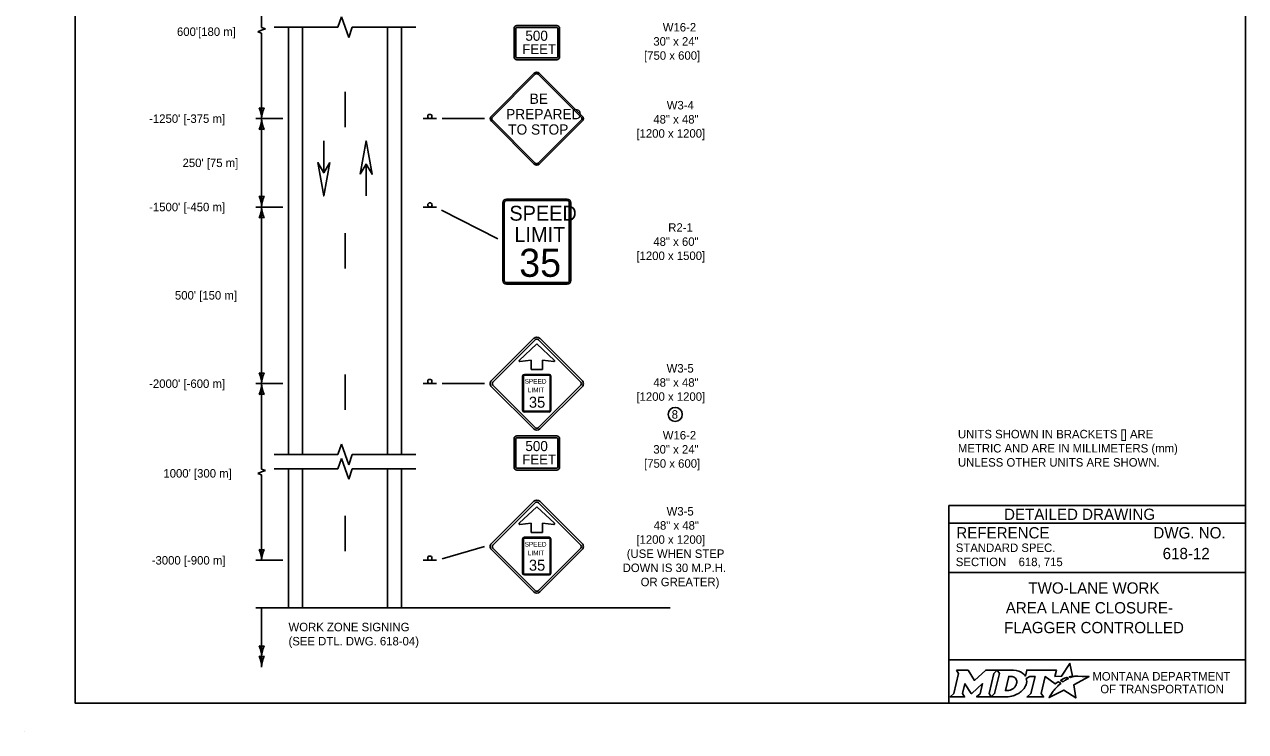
# Model space of a CAD drawing. Extents: x 49991.4 to 50021, y 49987.6 to 50011.4.
# Drawn here: x 49999.98 to 50008.61, y 49999.86 to 50004.87 of the extents above; entities that cross this region are included whole.
import ezdxf

# ---------------------------------------------------------------- set-up
doc = ezdxf.new("R2010")
doc.units = 0
for name, color, linetype in [('Level 1', 7, 'Continuous'), ('Level 2', 7, 'Continuous'), ('Level 3', 7, 'Continuous'), ('Level 6', 7, 'Continuous')]:
    doc.layers.add(name, color=color, linetype=linetype)

msp = doc.modelspace()

# ---------------------------------------------------------------- linework, layer by layer
at = {"layer": 'Level 1'}
for p, q in [((50001.8443, 50001.8221), (50001.8443, 50004.8471)), ((50001.9443, 50004.8119), (50001.9443, 50004.8482)), ((50001.9443, 50001.8221), (50001.9443, 50004.8471)), ((50002.5443, 50001.8221), (50002.5443, 50004.8471)), ((50002.6443, 50001.8221), (50002.6443, 50004.8471)), ((50003.4399, 50004.8376), (50003.4399, 50004.636)), ((50003.4533, 50004.636), (50003.4533, 50004.8376)), ((50003.7423, 50004.8577), (50003.46, 50004.8577)), ((50003.46, 50004.8443), (50003.7423, 50004.8443)), ((50003.749, 50004.8376), (50003.749, 50004.636)), ((50003.7624, 50004.636), (50003.7624, 50004.8376)), ((50003.7423, 50004.6292), (50003.46, 50004.6292)), ((50003.46, 50004.6158), (50003.7423, 50004.6158)), ((50003.5835, 50004.5207), (50003.2794, 50004.2167)), ((50003.9229, 50004.2167), (50003.6188, 50004.5207)), ((50003.5905, 50004.5137), (50003.2865, 50004.2096)), ((50003.9158, 50004.2096), (50003.6118, 50004.5137)), ((50002.2443, 50004.1388), (50002.2443, 50004.3888)), ((50002.8923, 50004.1991), (50002.7963, 50004.1991)), ((50003.2794, 50004.1813), (50003.5835, 50003.8773)), ((50003.2865, 50004.1884), (50003.5905, 50003.8843)), ((50003.6118, 50003.8843), (50003.9158, 50004.1884)), ((50003.6188, 50003.8773), (50003.9229, 50004.1813)), ((50002.094, 50004.0422), (50002.094, 50003.8163)), ((50002.0943, 50004.0422), (50002.0943, 50003.8163)), ((50002.3937, 50003.652), (50002.3937, 50003.8779)), ((50002.394, 50003.652), (50002.394, 50003.8779)), ((50002.8926, 50003.5738), (50002.7966, 50003.5738)), ((50003.361, 50003.6039), (50003.361, 50003.0539)), ((50003.371, 50003.6039), (50003.371, 50003.0539)), ((50003.816, 50003.6289), (50003.386, 50003.6289)), ((50003.816, 50003.6189), (50003.386, 50003.6189)), ((50003.831, 50003.0539), (50003.831, 50003.6039)), ((50003.841, 50003.0539), (50003.841, 50003.6039)), ((50002.2443, 50003.1388), (50002.2443, 50003.3888)), ((50003.386, 50003.0389), (50003.816, 50003.0389)), ((50003.386, 50003.0289), (50003.816, 50003.0289)), ((50003.5796, 50002.6448), (50003.2803, 50002.3455)), ((50003.5897, 50002.6347), (50003.2904, 50002.3354)), ((50003.5796, 50002.6448), (50003.5796, 50002.6448)), ((50003.5897, 50002.6347), (50003.5897, 50002.6347)), ((50003.9116, 50002.3354), (50003.6123, 50002.6347)), ((50003.9217, 50002.3455), (50003.6224, 50002.6448)), ((50003.601, 50002.6063), (50003.4766, 50002.489)), ((50003.7254, 50002.489), (50003.601, 50002.6063)), ((50003.4806, 50002.4804), (50003.5607, 50002.4904)), ((50003.5607, 50002.4904), (50003.5607, 50002.4249)), ((50003.6413, 50002.4249), (50003.6413, 50002.4904)), ((50003.6413, 50002.4904), (50003.7213, 50002.4804)), ((50002.2443, 50002.1388), (50002.2443, 50002.3888)), ((50003.5006, 50002.136), (50003.5006, 50002.3773)), ((50003.5058, 50002.136), (50003.5058, 50002.3773)), ((50003.5131, 50002.3898), (50003.6878, 50002.3898)), ((50003.5131, 50002.3846), (50003.6878, 50002.3846)), ((50003.5607, 50002.4249), (50003.6413, 50002.4249)), ((50003.6005, 50002.3898), (50003.6005, 50002.3898)), ((50003.6951, 50002.3773), (50003.6951, 50002.136)), ((50003.7003, 50002.3773), (50003.7003, 50002.136)), ((50002.8923, 50002.3241), (50002.7963, 50002.3241)), ((50003.2803, 50002.3027), (50003.5796, 50002.0034)), ((50003.2904, 50002.3128), (50003.5897, 50002.0135)), ((50003.6123, 50002.0135), (50003.9116, 50002.3128)), ((50003.6224, 50002.0034), (50003.9217, 50002.3027)), ((50003.6878, 50002.1288), (50003.5131, 50002.1288)), ((50003.6878, 50002.1236), (50003.5131, 50002.1236)), ((50003.4397, 50001.9344), (50003.4397, 50001.7328)), ((50003.4531, 50001.7328), (50003.4531, 50001.9344)), ((50003.7421, 50001.9546), (50003.4599, 50001.9546)), ((50003.4599, 50001.9411), (50003.7421, 50001.9411)), ((50003.7488, 50001.9344), (50003.7488, 50001.7328)), ((50003.7623, 50001.7328), (50003.7623, 50001.9344)), ((50001.8443, 50000.7385), (50001.8443, 50001.7221)), ((50001.9443, 50000.7385), (50001.9443, 50001.7221)), ((50002.5443, 50000.7385), (50002.5443, 50001.7221)), ((50002.6443, 50000.7385), (50002.6443, 50001.7221)), ((50003.7421, 50001.7261), (50003.4599, 50001.7261)), ((50003.4599, 50001.7126), (50003.7421, 50001.7126)), ((50003.5796, 50001.4918), (50003.2803, 50001.1925)), ((50003.5897, 50001.4817), (50003.2904, 50001.1824)), ((50003.601, 50001.4533), (50003.4766, 50001.336)), ((50003.5796, 50001.4918), (50003.5796, 50001.4918)), ((50003.5897, 50001.4817), (50003.5897, 50001.4817)), ((50003.7254, 50001.336), (50003.601, 50001.4533)), ((50003.9116, 50001.1824), (50003.6123, 50001.4817)), ((50003.9217, 50001.1925), (50003.6224, 50001.4918)), ((50002.2443, 50001.1388), (50002.2443, 50001.3888)), ((50003.4806, 50001.3274), (50003.5607, 50001.3374)), ((50003.5607, 50001.3374), (50003.5607, 50001.2719)), ((50003.6413, 50001.2719), (50003.6413, 50001.3374)), ((50003.6413, 50001.3374), (50003.7213, 50001.3274)), ((50003.5131, 50001.2368), (50003.6878, 50001.2368)), ((50003.5607, 50001.2719), (50003.6413, 50001.2719)), ((50003.6005, 50001.2368), (50003.6005, 50001.2368)), ((50003.2803, 50001.1497), (50003.5796, 50000.8504)), ((50003.2904, 50001.1598), (50003.5897, 50000.8605)), ((50003.5006, 50000.983), (50003.5006, 50001.2243)), ((50003.5058, 50000.983), (50003.5058, 50001.2243)), ((50003.5131, 50001.2316), (50003.6878, 50001.2316)), ((50003.6123, 50000.8605), (50003.9116, 50001.1598)), ((50003.6224, 50000.8504), (50003.9217, 50001.1497)), ((50003.6951, 50001.2243), (50003.6951, 50000.983)), ((50003.7003, 50001.2243), (50003.7003, 50000.983)), ((50002.8923, 50001.0741), (50002.7963, 50001.0741)), ((50003.6878, 50000.9758), (50003.5131, 50000.9758)), ((50003.6878, 50000.9706), (50003.5131, 50000.9706)), ((49999.9766, 49999.8624), (49999.9766, 49999.8624))]:
    msp.add_line(p, q, dxfattribs=at)
for points in [[(50008.6146, 50011.2628), (50000.3356, 50011.2628), (50000.3356, 50000.0624), (50008.6146, 50000.0624)], [(50002.352, 50003.8056), (50002.3937, 50004.0421), (50002.4356, 50003.8056), (50002.3937, 50003.8778)], [(50002.136, 50003.8886), (50002.0943, 50003.6521), (50002.0524, 50003.8886), (50002.0943, 50003.8164)]]:
    msp.add_lwpolyline(points, close=True, dxfattribs=at)
for centre in [(50002.8443, 50004.2144), (50002.8446, 50003.5891), (50002.8443, 50002.3394), (50002.8443, 50001.0893)]:
    msp.add_circle(centre, 0.0152, dxfattribs=at)
for centre, radius, start, end in [((50003.46, 50004.8376), 0.0202, 90, 180), ((50003.46, 50004.8376), 0.00672, 90, 180), ((50003.7423, 50004.8376), 0.0202, 0, 90), ((50003.7423, 50004.8376), 0.00672, 0, 90), ((50003.46, 50004.636), 0.0202, 180, 270), ((50003.46, 50004.636), 0.00672, 180, 270), ((50003.7423, 50004.636), 0.00672, 270, 360), ((50003.7423, 50004.636), 0.0202, 270, 360), ((50003.6011, 50004.5031), 0.025, 45, 135), ((50003.6011, 50004.5031), 0.015, 45, 135), ((50003.2971, 50004.1991), 0.025, 135, 225), ((50003.2971, 50004.1991), 0.015, 135, 225), ((50003.9052, 50004.1991), 0.015, 315, 45.00024), ((50003.9052, 50004.1991), 0.025, 315, 45.00024), ((50003.6011, 50003.895), 0.025, 225, 314.99957), ((50003.6011, 50003.895), 0.015, 225, 314.99957), ((50003.386, 50003.6039), 0.025, 90, 180), ((50003.386, 50003.6039), 0.015, 90, 180), ((50003.816, 50003.6039), 0.025, 0, 90), ((50003.816, 50003.6039), 0.015, 0, 90), ((50003.386, 50003.0539), 0.025, 180, 270), ((50003.386, 50003.0539), 0.015, 180, 270), ((50003.816, 50003.0539), 0.025, 270, 0), ((50003.816, 50003.0539), 0.015, 270, 0), ((50003.601, 50002.6234), 0.0302, 45.00007, 134.99993), ((50003.601, 50002.6234), 0.016, 45.00007, 134.99993), ((50003.4801, 50002.4854), 0.00508, 134.62874, 275.82948), ((50003.7218, 50002.4854), 0.00509, 264.38259, 45.16491), ((50003.5131, 50002.3773), 0.0125, 90, 180), ((50003.5131, 50002.3773), 0.00728, 90, 180), ((50003.6878, 50002.3773), 0.0125, 360, 90), ((50003.6878, 50002.3773), 0.00728, 360, 90), ((50003.3017, 50002.3241), 0.0302, 134.99993, 225.00008), ((50003.3017, 50002.3241), 0.016, 134.99993, 225.00008), ((50003.9003, 50002.3241), 0.016, 314.99993, 45.00007), ((50003.9003, 50002.3241), 0.0302, 314.99993, 45.00008), ((50003.5131, 50002.136), 0.0125, 180, 270), ((50003.5131, 50002.136), 0.00728, 180, 270), ((50003.6878, 50002.136), 0.00728, 270, 360), ((50003.6878, 50002.136), 0.0125, 270, 360), ((50003.601, 50002.0248), 0.016, 225.00007, 314.99993), ((50003.4599, 50001.9344), 0.0202, 90, 180), ((50003.4599, 50001.9344), 0.00672, 90, 180), ((50003.601, 50002.0248), 0.0302, 225.00007, 314.99993), ((50003.7421, 50001.9344), 0.0202, 0, 90), ((50003.7421, 50001.9344), 0.00672, 0, 90), ((50003.4599, 50001.7328), 0.0202, 180, 270), ((50003.4599, 50001.7328), 0.00672, 180, 270), ((50003.7421, 50001.7328), 0.00672, 270, 360), ((50003.7421, 50001.7328), 0.0202, 270, 360), ((50003.601, 50001.4704), 0.0302, 45.00007, 134.99993), ((50003.601, 50001.4704), 0.016, 45.00007, 134.99993), ((50003.4801, 50001.3324), 0.00508, 134.62874, 275.82948), ((50003.7218, 50001.3324), 0.00509, 264.38259, 45.16491), ((50003.5131, 50001.2243), 0.0125, 90, 180), ((50003.6878, 50001.2243), 0.0125, 360, 90), ((50003.3017, 50001.1711), 0.0302, 134.99993, 225.00008), ((50003.3017, 50001.1711), 0.016, 134.99993, 225.00008), ((50003.5131, 50001.2243), 0.00728, 90, 180), ((50003.6878, 50001.2243), 0.00728, 360, 90), ((50003.9003, 50001.1711), 0.016, 314.99993, 45.00007), ((50003.9003, 50001.1711), 0.0302, 314.99993, 45.00008), ((50003.5131, 50000.983), 0.0125, 180, 270), ((50003.5131, 50000.983), 0.00728, 180, 270), ((50003.6878, 50000.983), 0.00728, 270, 360), ((50003.6878, 50000.983), 0.0125, 270, 360), ((50003.601, 50000.8718), 0.0302, 225.00007, 314.99993), ((50003.601, 50000.8718), 0.016, 225.00007, 314.99993)]:
    msp.add_arc(centre, radius, start, end, dxfattribs=at)
at = {"layer": 'Level 2'}
for p, q in [((50008.6146, 50001.4624), (50006.5146, 50001.4624)), ((50006.5146, 50001.4624), (50006.5146, 50000.0624)), ((50008.6146, 50001.3374), (50006.5146, 50001.3374)), ((50008.2507, 50001.1223), (50008.2507, 50001.1223)), ((50008.6146, 50000.9874), (50006.5146, 50000.9874)), ((50007.0089, 50001.0629), (50007.0089, 50001.0629)), ((50007.5646, 50000.7383), (50007.5646, 50000.7383)), ((50008.6146, 50000.3693), (50006.5146, 50000.3693))]:
    msp.add_line(p, q, dxfattribs=at)
for points in [[(50006.5701, 50000.2974), (50006.5842, 50000.274), (50006.5507, 50000.1307), (50006.525, 50000.1082), (50006.6266, 50000.1082), (50006.6131, 50000.131), (50006.6293, 50000.2011), (50006.673, 50000.1321), (50006.6783, 50000.1321), (50006.7534, 50000.2016), (50006.737, 50000.1305), (50006.7123, 50000.1085), (50006.8139, 50000.1085), (50006.8001, 50000.1318), (50006.8333, 50000.2742)], [(50006.8333, 50000.2742), (50006.8586, 50000.2974), (50006.7762, 50000.2974), (50006.6966, 50000.2244), (50006.6521, 50000.2971), (50006.5701, 50000.2974)], [(50006.9722, 50000.2974), (50006.8586, 50000.2974), (50006.8733, 50000.2745), (50006.8394, 50000.1307), (50006.8139, 50000.1085), (50006.9245, 50000.1085)], [(50007.3771, 50000.2447), (50007.3668, 50000.2503), (50007.3784, 50000.2531), (50007.39, 50000.2551), (50007.3726, 50000.3452), (50007.3131, 50000.2539), (50007.2658, 50000.2532), (50007.2761, 50000.2973), (50007.0669, 50000.2974), (50007.0568, 50000.2549), (50007.051, 50000.2632)], [(50006.9962, 50000.2107), (50006.995, 50000.2026), (50006.9918, 50000.1933), (50006.9876, 50000.1851), (50006.982, 50000.1776), (50006.9755, 50000.1707), (50006.9676, 50000.1644), (50006.9593, 50000.1597), (50006.9502, 50000.1558), (50006.9411, 50000.1535), (50006.9319, 50000.1526), (50006.916, 50000.1526), (50006.9396, 50000.2526), (50006.9556, 50000.2526), (50006.9632, 50000.252), (50006.9708, 50000.2501), (50006.9774, 50000.2471), (50006.9835, 50000.2429), (50006.9883, 50000.2379), (50006.992, 50000.2319), (50006.9947, 50000.2257), (50006.9963, 50000.2183), (50006.9963, 50000.2153), (50006.9962, 50000.2107)], [(50007.0636, 50000.2383), (50007.0882, 50000.2514), (50007.1251, 50000.2514), (50007.0965, 50000.1309), (50007.069, 50000.1082), (50007.1852, 50000.1082), (50007.1682, 50000.1311), (50007.1964, 50000.2513), (50007.2677, 50000.1996), (50007.2888, 50000.2147), (50007.3085, 50000.2038)], [(50007.2527, 50000.1479), (50007.2374, 50000.1235), (50007.2327, 50000.116), (50007.2269, 50000.1074), (50007.2246, 50000.1031), (50007.3299, 50000.1562), (50007.4138, 50000.1011), (50007.4007, 50000.1938), (50007.5076, 50000.2522), (50007.4583, 50000.253), (50007.4282, 50000.2534), (50007.4074, 50000.2537), (50007.4006, 50000.2522), (50007.3957, 50000.251), (50007.3873, 50000.2487), (50007.3771, 50000.2447)], [(50007.3267, 50000.2171), (50007.3243, 50000.2154), (50007.306, 50000.225), (50007.3163, 50000.2307), (50007.3204, 50000.2329), (50007.329, 50000.2369), (50007.3347, 50000.2395), (50007.3426, 50000.2425), (50007.3499, 50000.2452), (50007.3617, 50000.2378), (50007.3577, 50000.2357), (50007.3531, 50000.2332), (50007.3489, 50000.231), (50007.3439, 50000.2281), (50007.342, 50000.227), (50007.3393, 50000.2254), (50007.3368, 50000.224), (50007.3345, 50000.2224), (50007.3319, 50000.2206), (50007.3292, 50000.2188), (50007.3267, 50000.2171)], [(50006.9702, 50000.1158), (50006.9786, 50000.1184), (50006.9916, 50000.1238), (50007.012, 50000.1348)], [(50007.2666, 50000.164), (50007.2666, 50000.164)]]:
    msp.add_lwpolyline(points, dxfattribs=at)
msp.add_circle((50004.5801, 50002.1065), 0.05, dxfattribs=at)
for centre, radius, start, end in [((50006.9953, 50000.219), 0.0709, 339.53292, 15.85821), ((50006.9513, 50000.2363), 0.1183, 300.91025, 339.13831)]:
    msp.add_arc(centre, radius, start, end, dxfattribs=at)
for centre, major_axis, ratio, start_param, end_param in [((50006.9701, 50000.25), (0.0834, -0.0037), 0.568097, 0.61298, 1.570796), ((50007.0257, 50000.2573), (0.0361, -0.0295), 0.469099, 1.225588, 1.570796), ((50007.2974, 50000.1941), (-0.0112, -0.0097), 0.021651, 3.157348, 6.283185), ((50006.9248, 50000.2568), (0, 0.1484), 0.987302, 3.139398, 3.456847), ((50007.2597, 50000.1559), (-0.00694, -0.00806), 0.008222, 0, 3.137361), ((50007.2764, 50000.1742), (-0.0098, -0.0102), 0.016458, 3.141593, 6.279097)]:
    msp.add_ellipse(centre, major_axis=major_axis, ratio=ratio, start_param=start_param, end_param=end_param, dxfattribs=at)
at = {"layer": 'Level 3'}
for p, q in [((50001.6546, 50004.8434), (50001.6546, 50005.3709)), ((50001.6543, 50004.8241), (50001.6269, 50004.8144)), ((50001.6546, 50004.8046), (50001.6269, 50004.8144)), ((50001.6817, 50004.8338), (50001.6543, 50004.8241)), ((50001.6817, 50004.8338), (50001.6546, 50004.8434)), ((50001.6546, 50004.8046), (50001.6546, 50004.1991)), ((50001.6546, 50004.1991), (50001.6146, 50004.1991)), ((50001.6546, 50004.1991), (50001.8043, 50004.1991)), ((50001.6546, 50004.1991), (50001.6546, 50003.5738)), ((50002.9323, 50004.1991), (50003.2321, 50004.1991)), ((50001.6546, 50003.5738), (50001.6146, 50003.5738)), ((50001.6546, 50003.5738), (50001.8043, 50003.5738)), ((50001.6546, 50003.5738), (50001.6546, 50002.3241)), ((50002.9265, 50003.5526), (50003.3258, 50003.3479)), ((50001.6546, 50002.3241), (50001.6146, 50002.3241)), ((50001.6546, 50002.3241), (50001.8043, 50002.3241)), ((50001.6546, 50002.3241), (50001.6546, 50001.7184)), ((50002.9323, 50002.3241), (50003.2315, 50002.3241)), ((50001.6546, 50001.6992), (50001.6269, 50001.6894)), ((50001.6546, 50001.6796), (50001.6269, 50001.6894)), ((50001.6817, 50001.7088), (50001.6546, 50001.7184)), ((50001.6817, 50001.7088), (50001.6546, 50001.6992)), ((50001.6546, 50001.0741), (50001.6546, 50001.6796)), ((50002.9309, 50001.0846), (50003.2315, 50001.1711)), ((50001.6546, 50001.0741), (50001.6146, 50001.0741)), ((50001.6546, 50001.0741), (50001.8043, 50001.0741)), ((50001.6546, 50000.7385), (50001.6146, 50000.7385)), ((50001.6546, 50000.7385), (50001.6546, 50000.3188)), ((50001.6546, 50000.7385), (50004.5444, 50000.7385))]:
    msp.add_line(p, q, dxfattribs=at)
for centre, radius, start, end in [((50001.6546, 50004.3273), 0.0548, 252.13882, 287.86118), ((50001.4219, 50004.1876), 0.233, 2.82731, 22.07716), ((50001.8767, 50004.1899), 0.2223, 157.45601, 177.63952), ((50001.4324, 50004.2082), 0.2223, 337.45601, 357.63952), ((50001.8873, 50004.2106), 0.233, 182.82731, 202.07716), ((50001.6546, 50004.0709), 0.0548, 72.13882, 107.86118), ((50001.6546, 50003.702), 0.0548, 252.13882, 287.86118), ((50001.4219, 50003.5623), 0.233, 2.82731, 22.07716), ((50001.4324, 50003.583), 0.2223, 337.45601, 357.63952), ((50001.8767, 50003.5647), 0.2223, 157.45601, 177.63952), ((50001.8873, 50003.5853), 0.233, 182.82731, 202.07716), ((50001.6546, 50003.4456), 0.0548, 72.13882, 107.86118), ((50001.6546, 50002.4523), 0.0548, 252.13882, 287.86118), ((50001.4219, 50002.3126), 0.233, 2.82731, 22.07716), ((50001.8767, 50002.3149), 0.2223, 157.45601, 177.63952), ((50001.4324, 50002.3332), 0.2223, 337.45601, 357.63952), ((50001.8873, 50002.3356), 0.233, 182.82731, 202.07716), ((50001.6546, 50002.1959), 0.0548, 72.13882, 107.86118), ((50001.6546, 50001.2023), 0.0548, 252.13882, 287.86118), ((50001.4219, 50001.0626), 0.233, 2.82731, 22.07716), ((50001.8767, 50001.0649), 0.2223, 157.45601, 177.63952), ((50001.6546, 50000.5204), 0.0548, 252.13882, 287.86118), ((50001.4219, 50000.3807), 0.233, 2.82731, 22.07716), ((50001.8767, 50000.3831), 0.2223, 157.45601, 177.63952), ((50001.6546, 50000.447), 0.0548, 252.13882, 287.86118), ((50001.4219, 50000.3073), 0.233, 2.82731, 22.07716), ((50001.8767, 50000.3096), 0.2223, 157.45601, 177.63952)]:
    msp.add_arc(centre, radius, start, end, dxfattribs=at)
at = {"layer": 'Level 6'}
for p, q in [((50002.2184, 50004.9202), (50002.1925, 50004.8471)), ((50002.2184, 50004.9202), (50002.2443, 50004.8471)), ((50002.1925, 50004.8471), (50001.7443, 50004.8471)), ((50002.2443, 50004.8471), (50002.2702, 50004.774)), ((50002.2961, 50004.8471), (50002.2702, 50004.774)), ((50002.7443, 50004.8471), (50002.2961, 50004.8471)), ((50002.2184, 50001.8952), (50002.1925, 50001.8221)), ((50002.2184, 50001.8952), (50002.2443, 50001.8221)), ((50001.7443, 50001.8221), (50002.1925, 50001.8221)), ((50002.2184, 50001.7952), (50002.1925, 50001.7221)), ((50002.2184, 50001.7952), (50002.2443, 50001.7221)), ((50002.2443, 50001.8221), (50002.2702, 50001.749)), ((50002.2961, 50001.8221), (50002.2702, 50001.749)), ((50002.2961, 50001.8221), (50002.7443, 50001.8221)), ((50002.1925, 50001.7221), (50001.7443, 50001.7221)), ((50002.2443, 50001.7221), (50002.2702, 50001.649)), ((50002.2961, 50001.7221), (50002.2702, 50001.649)), ((50002.7443, 50001.7221), (50002.2961, 50001.7221))]:
    msp.add_line(p, q, dxfattribs=at)

# ---------------------------------------------------------------- texts
at = {"layer": 'Level 1'}
for s, height, p in [('500', 0.07124, (50003.5202, 50004.7502)), ('FEET', 0.06989, (50003.4979, 50004.6561)), ('BE', 0.0725, (50003.5508, 50004.3036)), ('PREPARED', 0.0725, (50003.3839, 50004.1948)), ('TO STOP', 0.0725, (50003.3986, 50004.0861)), ('SPEED', 0.10512, (50003.4072, 50003.4773)), ('LIMIT', 0.10512, (50003.4427, 50003.3272)), ('35', 0.19892, (50003.4767, 50003.0799)), ('500', 0.07124, (50003.5201, 50001.847)), ('FEET', 0.06989, (50003.4977, 50001.7529))]:
    msp.add_text(s, height=height, dxfattribs=at).set_placement(p)
for s, height, p in [('SPEED', 0.03301, (50003.5151, 50002.3241)), ('LIMIT', 0.03301, (50003.537, 50002.2631)), ('35', 0.07775, (50003.545, 50002.1537)), ('SPEED', 0.03301, (50003.5151, 50001.1711)), ('LIMIT', 0.03301, (50003.537, 50001.1101)), ('35', 0.07775, (50003.545, 50001.0007))]:
    msp.add_text(s, height=height, rotation=360, dxfattribs=at).set_placement(p)
at = {"layer": 'Level 2'}
for s, height, p in [('W16-2', 0.06, (50004.492, 50004.8158)), ("600'[180 m]", 0.06, (50001.0556, 50004.7844)), ('30" x 24"', 0.06, (50004.4252, 50004.7158)), ('[750 x 600]', 0.06, (50004.3596, 50004.6158)), ('W3-4', 0.06, (50004.5202, 50004.2645)), ("-1250' [-375 m]", 0.06, (50000.8588, 50004.1691)), ('48" x 48"', 0.06, (50004.4252, 50004.1645)), ('[1200 x 1200]', 0.06, (50004.3057, 50004.0645)), ("250' [75 m]", 0.06, (50001.0951, 50003.8565)), ("-1500' [-450 m]", 0.06, (50000.8588, 50003.5438)), ('R2-1', 0.06, (50004.5307, 50003.399)), ('48" x 60"', 0.06, (50004.4252, 50003.299)), ('[1200 x 1500]', 0.06, (50004.3057, 50003.199)), ("500' [150 m]", 0.06, (50001.0412, 50002.919)), ('W3-5', 0.05999, (50004.5193, 50002.4026)), ('48" x 48"', 0.05999, (50004.4253, 50002.3026)), ("-2000' [-600 m]", 0.06, (50000.8588, 50002.2941)), ('[1200 x 1200]', 0.059993, (50004.3059, 50002.2026)), ('8', 0.06, (50004.5552, 50002.0765)), ('W16-2', 0.05999, (50004.4921, 50001.9292)), ('UNITS SHOWN IN BRACKETS [] ARE ', 0.06, (50006.5799, 50001.9371)), ('30" x 24"', 0.05999, (50004.4252, 50001.8292)), ('METRIC AND ARE IN MILLIMETERS (mm) ', 0.06, (50006.5799, 50001.8371)), ('[750 x 600]', 0.059993, (50004.3596, 50001.7293)), ('UNLESS OTHER UNITS ARE SHOWN.', 0.06, (50006.5799, 50001.7371)), ("1000' [300 m]", 0.06, (50000.9596, 50001.6594)), ('W3-5', 0.06, (50004.5192, 50001.3911)), ('DETAILED DRAWING', 0.0799, (50006.9063, 50001.3599)), ('  48" x 48" ', 0.06, (50004.3831, 50001.2911)), ('[1200 x 1200]', 0.06, (50004.3057, 50001.1911)), ('REFERENCE', 0.08, (50006.5682, 50001.229)), ('DWG. NO.', 0.08, (50007.9624, 50001.229)), ('(USE WHEN STEP', 0.06, (50004.2371, 50001.0911)), ('STANDARD SPEC.', 0.06, (50006.5649, 50001.133)), ('618-12', 0.08, (50008.0281, 50001.0823)), ('-3000 [-900 m]', 0.06, (50000.8769, 50001.0441)), ('SECTION', 0.06, (50006.5649, 50001.033)), ('618, 715', 0.06, (50007.0089, 50001.0329)), ('DOWN IS 30 M.P.H.', 0.06, (50004.2082, 50000.9911)), ('OR GREATER)', 0.06, (50004.3354, 50000.8911)), (' TWO-LANE WORK', 0.08, (50007.0488, 50000.8383)), ('  AREA LANE CLOSURE-', 0.08, (50006.8587, 50000.6983)), ('WORK ZONE SIGNING', 0.06, (50001.8446, 50000.5721)), ('FLAGGER CONTROLLED', 0.08, (50006.9062, 50000.5583)), ('(SEE DTL. DWG. 618-04)', 0.06, (50001.8446, 50000.4721)), ('MONTANA DEPARTMENT', 0.06, (50007.5308, 50000.2236)), ('OF TRANSPORTATION', 0.06, (50007.587, 50000.1336))]:
    msp.add_text(s, height=height, dxfattribs=at).set_placement(p)

doc.saveas('drawing.dxf')
